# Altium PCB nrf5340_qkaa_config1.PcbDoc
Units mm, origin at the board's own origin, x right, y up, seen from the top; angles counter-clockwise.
Board outline 17 x 15 mm, 4 copper layers (Top Layer, Mid Layer 1, Mid Layer 2, Bottom Layer), stack 1.583 mm thick; 29 components, 70 nets, 204 pads, 111 vias.
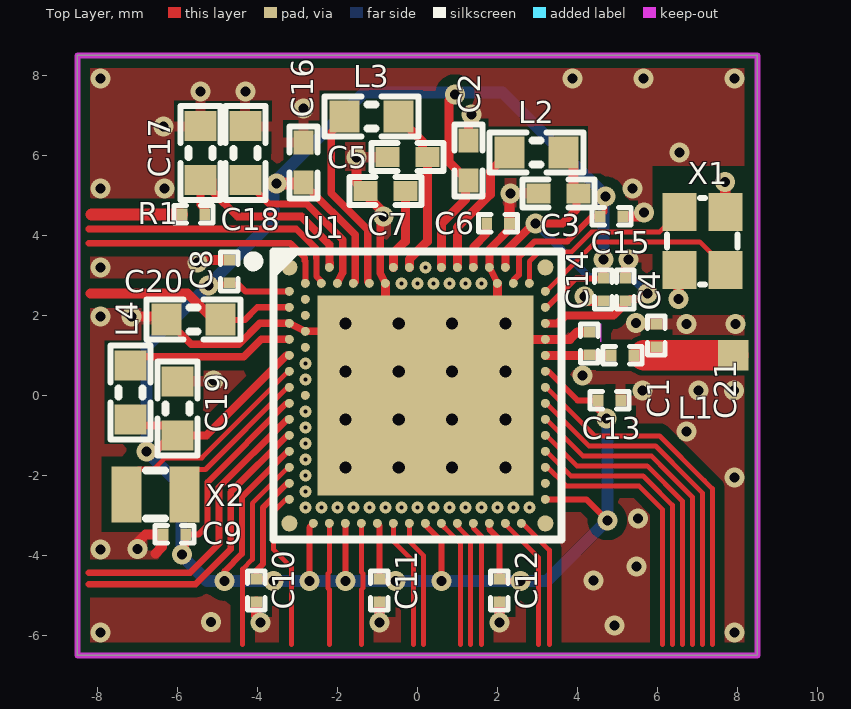
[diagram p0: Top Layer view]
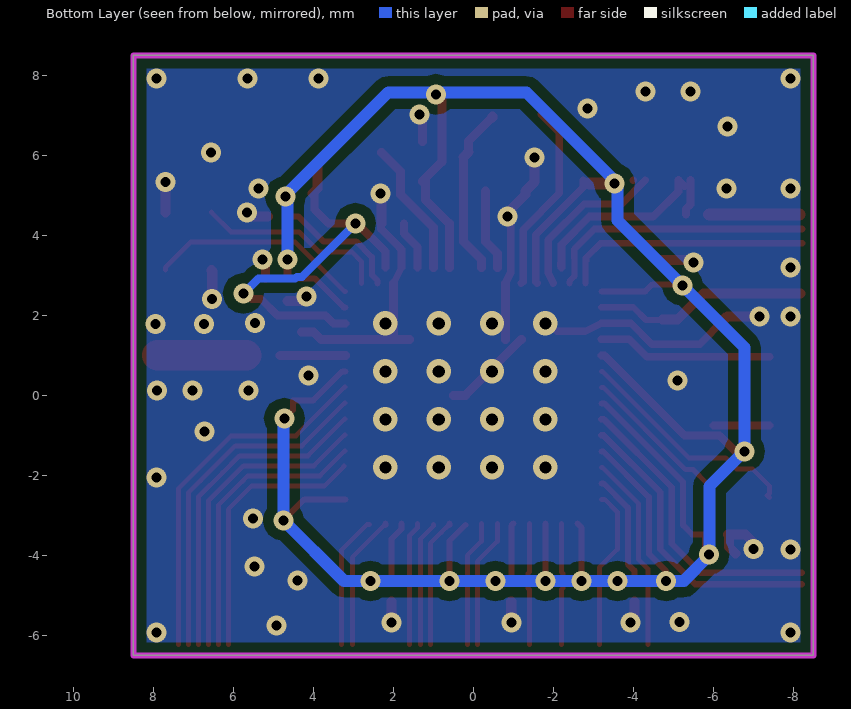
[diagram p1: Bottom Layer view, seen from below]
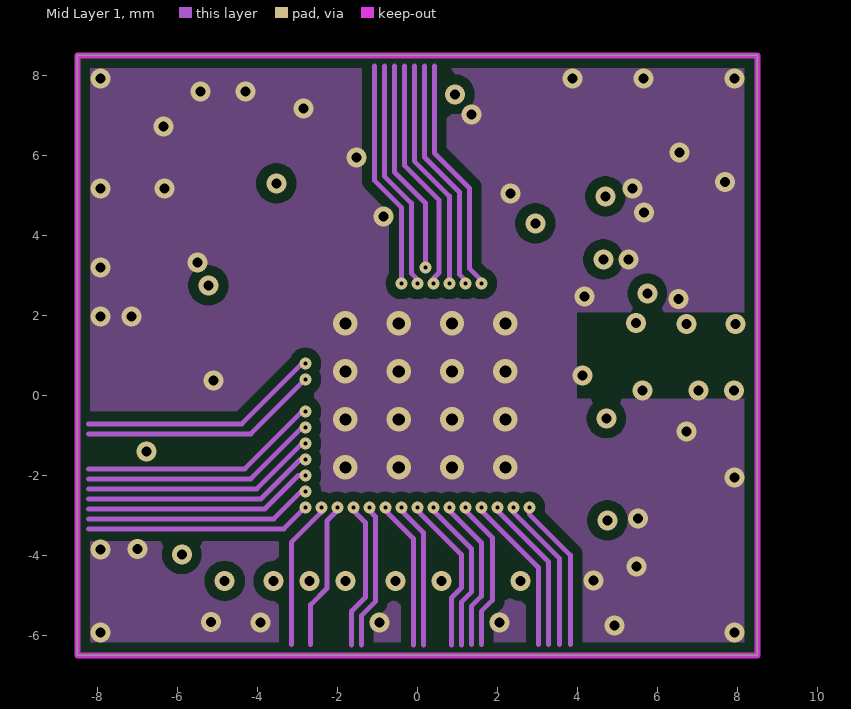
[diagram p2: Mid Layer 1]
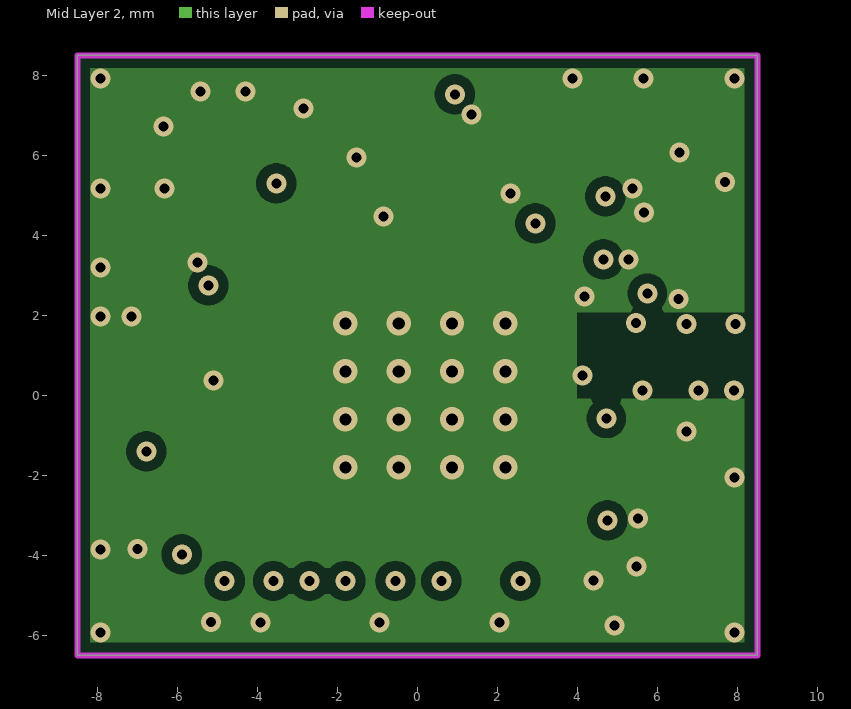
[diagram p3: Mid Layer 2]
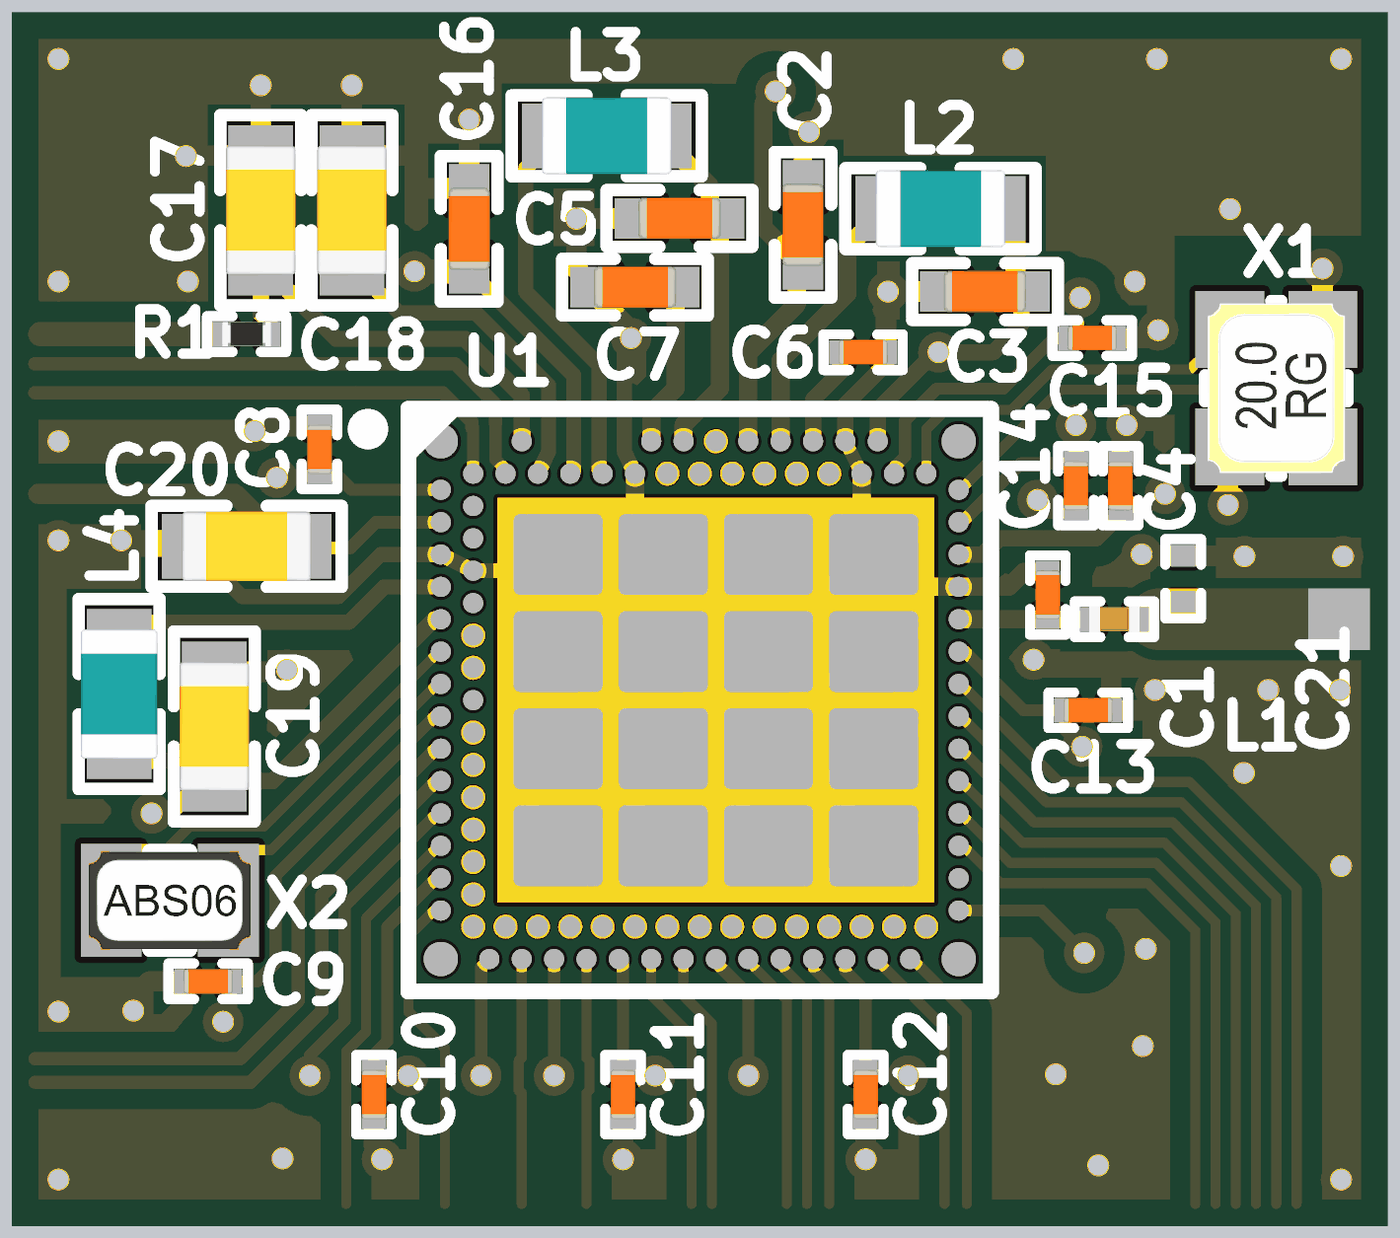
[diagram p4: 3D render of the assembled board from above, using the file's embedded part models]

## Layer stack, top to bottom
Top Solder: solder mask 0.0102, Solder Resist, Dk 3.5
Top Layer: signal copper 0.0356
Dielectric1: core 0.07, FR-4, Dk 4.8
Mid Layer 1: signal copper 0.036
Dielectric 3: prepreg 1.3, Dk 4.2
Mid Layer 2: signal copper 0.036
Dielectric 2: core 0.07, Dk 4.2
Bottom Layer: signal copper 0.0356
Bottom Solder: solder mask 0.0102, Solder Resist, Dk 3.5

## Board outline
-8.5,-6.5 8.5,-6.5 8.5,8.5 -8.5,8.5

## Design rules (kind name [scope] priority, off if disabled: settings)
Clearance Clearance_microvia [AsMM(ViaDiameter) = 0.3 vs AsMM(ViaDiameter) = 0.3] p1: gap=0.1 ignorepadtopadclearanceinfootprint=FALSE
Clearance Polygon_ANT [(InNamedPolygon('Top_Layer-GND')) or  (InNamedPolygon('Mid_Layer_1-GND')) or (InNamedPolygon('Mid_Layer_2-GND')) or (InNamedPolygon('Bottom_Layer-GND')) vs InNet('RF')] p2: gap=0.127 ignorepadtopadclearanceinfootprint=FALSE except(0: Arc-Hole Track-Hole SMDPad-Hole THPad-Hole Via-Hole Fill-Hole Poly-Hole Region-Hole Text-Hole)
Clearance Polygon [(InNamedPolygon('Top_Layer-GND')) or  (InNamedPolygon('Mid_Layer_1-GND')) or (InNamedPolygon('Mid_Layer_2-GND')) or (InNamedPolygon('Bottom_Layer-GND'))] p3: gap=0.25 ignorepadtopadclearanceinfootprint=FALSE
Clearance Clearance_Top [OnTopLayer] p4: gap=0.125 ignorepadtopadclearanceinfootprint=FALSE
Clearance [All] p5: gap=0.125 ignorepadtopadclearanceinfootprint=FALSE
ComponentClearance [All] p1 off: gap=0.254 collisioncheckmode=3 verticalgap=0.254 showdistances=FALSE
DiffPairsRouting [All] p1: maxlimit=0.193 minlimit=0.193 mostfreqgap=0.193 toplayer_minwidth=0.125 toplayer_maxwidth=0.381 toplayer_prefwidth=0.165 midlayer1_minwidth=0.125 midlayer1_maxwidth=0.381 midlayer1_prefwidth=0.165 midlayer2_minwidth=0.125 midlayer2_maxwidth=0.381 midlayer2_prefwidth=0.165 bottomlayer_minwidth=0.125 bottomlayer_maxwidth=0.381 bottomlayer_prefwidth=0.165 maxuncoupledlength=12.7
FabricationTestPointUsage TestPointUsage [All] p1: valid=0 allowmultiple=FALSE
FabricationTestpoint Testpoint [All] p1: side=3 testpointundercomponent=TRUE minsize=1.016 maxsize=2.54 preferedsize=1.524 minholesize=0 maxholesize=1.016 preferedholesize=0.813 testpointgrid=0.025 allowsidetop=TRUE allowsidebottom=TRUE usegrid=TRUE gridtolerance=0
Height [All] p1 off: minheight=0 maxheight=25.4 prefheight=12.7
HoleSize [All] p1: absolutevalues=TRUE maxlimit=4.064 minlimit=0.1 maxpercent=80.000 minpercent=20.000
MinimumAnnularRing [All] p1 off: minimumring=0.152
PolygonConnect PolygonConnect_1 [isVia and innet(gnd)] p1: connectstyle=Direct reliefconductorwidth=0.254 reliefentries=4 polygonreliefangle="90 Angle" airgapwidth=0.254
PolygonConnect [All] p2: connectstyle=Relief reliefconductorwidth=0.254 reliefentries=4 polygonreliefangle="90 Angle" airgapwidth=0.254
RoutingVias [All] p1: holewidth=0.305 width=0.61 viastyle="Through Hole" minholewidth=0.1 minwidth=0.3 maxholewidth=0.305 maxwidth=0.61
SilkToSolderMaskClearance SilkscreenOverComponentPads [IsPad] p1: minsilkscreentomaskgap=0.254 clearancetoexposedcopper=TRUE
SolderMaskExpansion [All] p1: expansion=0.076 istentingtop=FALSE
Width [All] p1: maxlimit=2 minlimit=0.125 preferedwidth=0.125 minimp=50.000000 maximp=50.000000 favimp=50.000000
23 further rules are at their usual default settings.

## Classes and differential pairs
differential pair D: +D_P -D_N

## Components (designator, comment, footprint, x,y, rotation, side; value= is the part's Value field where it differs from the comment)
C1 "0.7pF" CAPC0603X03L_C 4.3,1.3 r270 top
C2 "1.0µF" CAPC1005X04L 1.275,5.875 r90 top
C3 "1.0µF" CAPC1005X04L 3.525,5.05 r0 top
C4 "2.2nF" CAPC0603X03L_C 5.2,2.65 r90 top
C5 "1.0µF" CAPC1005X04L -0.25,5.955 r0 top
C6 "100nF" CAPC0603X03L_C 2.019,4.3 r0 top
C7 "1.0µF" CAPC1005X04L -0.8,5.105 r0 top
C8 "100nF" CAPC0603X03L_C -4.7,3.1 r90 top
C9 "100nF" CAPC0603X03L_C -6.075,-3.475 r180 top
C10 "100nF" CAPC0603X03L_C -4.026,-4.875 r270 top
C11 "100nF" CAPC0603X03L_C -0.948,-4.875 r270 top
C12 "100nF" CAPC0603X03L_C 2.05,-4.875 r270 top
C13 "100nF" CAPC0603X03L_C 4.8,-0.125 r0 top
C14 "100nF" CAPC0603X03L_C 4.65,2.65 r270 top
C15 "100nF" CAPC0603X03L_C 4.85,4.475 r0 top
C16 "1.0µF" CAPC1005X04L -2.85,5.825 r270 top
C17 "4.7µF" CAPC1608X06L -5.425,6.055 r90 top
C18 "4.7µF" CAPC1608X06L -4.3,6.055 r90 top
C19 "2.2µF" CAPC1608X06L -6,-0.325 r90 top
C20 "4.7µF" CAPC1608X06L -5.6,1.9 r180 top
C21 "N.C." CAPC0603X03L_C_NC 5.975,1.5 r270 top
L1 "2.2nH" INDC0603X03L_C 5.125,1 r180 top
L2 "10µH" INDC1608X06L 2.975,6.075 r180 top
L3 "10µH" INDC1608X06L -1.15,6.975 r180 top
L4 "10µH" INDC1608X06L -7.175,0.075 r270 top
R1 "2R2" RESC0603X03L_C -5.6,4.525 r0 top
U1 "nRF5340-QKAA" AQFN40P700X700X85_HS-99N 0,0 r0 top locked
X1 "32MHz" BT-XTAL_2016 7.125,3.854 r90 top
X2 "32.768kHz" XTAL_2012 -6.55,-2.475 r0 top

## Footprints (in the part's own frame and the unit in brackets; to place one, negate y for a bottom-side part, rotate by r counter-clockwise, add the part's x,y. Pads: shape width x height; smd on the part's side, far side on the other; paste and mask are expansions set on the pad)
AQFN40P700X700X85_HS-99N [mm] "AQFN, 98-Leads, Body 7.00x7.00mm, Pitch 0.40mm, Thermal Pad 5.4x5.0mm, IPC Medium Density"
  rect 5.4x5 smd paste-5 mask+0.05: 104(0.2,0)
  round 0.4 smd paste+0.012 mask+0.05: A1(-3.2,3.2) A31(3.2,3.2) AL1(-3.2,-3.2) AL31(3.2,-3.2)
  round 0.225 smd paste+0.012 mask+0.05: A5(-2.2,3.2) A13(-0.6,3.2) A15(-0.2,3.2) A17(0.2,3.2) A19(0.6,3.2) A21(1,3.2) A23(1.4,3.2) A25(1.8,3.2) A27(2.2,3.2) AA1(-3.2,-1) AA31(3.2,-1) AB2(-2.8,-1.2) AC1(-3.2,-1.4) AC31(3.2,-1.4) AD2(-2.8,-1.6) AE1(-3.2,-1.8) AE31(3.2,-1.8) AF2(-2.8,-2) AG1(-3.2,-2.2) AG31(3.2,-2.2) AH2(-2.8,-2.4) AJ1(-3.2,-2.6) AJ31(3.2,-2.6) AK2(-2.8,-2.8) AK4(-2.4,-2.8) AK6(-2,-2.8) AK8(-1.6,-2.8) AK10(-1.2,-2.8) AK12(-0.8,-2.8) AK14(-0.4,-2.8) AK16(0,-2.8) AK18(0.4,-2.8) AK20(0.8,-2.8) AK22(1.2,-2.8) AK24(1.6,-2.8) AK26(2,-2.8) AK28(2.4,-2.8) AK30(2.8,-2.8) AL3(-2.6,-3.2) AL5(-2.2,-3.2) AL7(-1.8,-3.2) AL9(-1.4,-3.2) AL11(-1,-3.2) AL13(-0.6,-3.2) AL15(-0.2,-3.2) AL17(0.2,-3.2) AL19(0.6,-3.2) AL21(1,-3.2) AL23(1.4,-3.2) AL25(1.8,-3.2) AL27(2.2,-3.2) AL29(2.6,-3.2) B2(-2.8,2.8) B4(-2.4,2.8) B6(-2,2.8) B8(-1.6,2.8) B10(-1.2,2.8) B12(-0.8,2.8) B14(-0.4,2.8) B16(0,2.8) B18(0.4,2.8) B20(0.8,2.8) B22(1.2,2.8) B24(1.6,2.8) B26(2,2.8) B28(2.4,2.8) B30(2.8,2.8) C1(-3.2,2.6) C31(3.2,2.6) D2(-2.8,2.4) E1(-3.2,2.2) E31(3.2,2.2) F2(-2.8,2) G1(-3.2,1.8) G31(3.2,1.8) H2(-2.8,1.6) J1(-3.2,1.4) J31(3.2,1.4) K2(-2.8,1.2) L1(-3.2,1) L31(3.2,1) M2(-2.8,0.8) N1(-3.2,0.6) N31(3.2,0.6) P2(-2.8,0.4) R1(-3.2,0.2) R31(3.2,0.2) T2(-2.8,0) U1(-3.2,-0.2) U31(3.2,-0.2) V2(-2.8,-0.4) W1(-3.2,-0.6) W31(3.2,-0.6) Y2(-2.8,-0.8)
  rrect15% 1.1x1 on Top Paste: ""(-1.75,-1.8) ""(-1.75,-0.6) ""(-1.75,0.6) ""(-1.75,1.8) ""(-0.45,-1.8) ""(-0.45,-0.6) ""(-0.45,0.6) ""(-0.45,1.8) ""(0.85,-1.8) ""(0.85,-0.6) ""(0.85,0.6) ""(0.85,1.8) ""(2.15,-1.8) ""(2.15,-0.6) ""(2.15,0.6) ""(2.15,1.8)
  silkscreen extent -4.22,-3.6 3.6,3.6, body extent -3.5,-3.5 3.5,3.5, height 0.85
BT-XTAL_2016 [mm] "Crystal 2.0 x 1.6 mm"
  rect 0.95x0.85 smd: 1(-0.725,-0.575) 2(0.725,-0.575) 3(0.725,0.575) 4(-0.725,0.575)
  silkscreen extent -1.08,-0.88 1.08,0.88, body extent -1.05,-0.85 1.05,0.85, height 0.56
CAPC0603X03L_C [mm] "Chip Capacitor, 2-Leads, Body 0.6x0.3mm, IPC High Density"
  rect 0.27x0.3 smd: 1(-0.285,0) 2(0.285,0)
  silkscreen extent -0.49,-0.22 0.49,0.22, body extent -0.3,-0.15 0.31,0.15, height 0.3
CAPC0603X03L_C_NC [mm] "Chip Capacitor, 2-Leads, Body 0.6x0.3mm, IPC High Density"
  rect 0.27x0.3 smd mask+0.05: 1(-0.285,0) 2(0.285,0)
  silkscreen extent -0.49,-0.22 0.49,0.22
CAPC1005X04L [mm] "Chip Capacitor, 2-Leads, Body 1.0x0.5mm, IPC High Density"
  rect 0.6x0.5 smd: 1(-0.5,0) 2(0.5,0)
  silkscreen extent -0.9,-0.35 0.9,0.35, body extent -0.51,-0.25 0.51,0.25, height 0.5
CAPC1608X06L [mm] "Chip Capacitor, 2-Leads, Body 1.6x0.8mm, IPC High Density"
  rect 0.75x0.8 smd: 1(-0.675,0) 2(0.675,0)
  silkscreen extent -1.17,-0.5 1.17,0.5, body extent -0.8,-0.43 0.8,0.43, height 0.8
INDC0603X03L_C [mm] "Chip Inductor, 2-Leads, Body 0.6x0.3mm, IPC High Density"
  rect 0.27x0.3 smd: 1(-0.285,0) 2(0.285,0)
  silkscreen extent -0.49,-0.22 0.49,0.22, body extent -0.31,-0.16 0.31,0.16, height 0.26
INDC1608X06L [mm] "Chip Inductor, 2-Leads, Body 1.6x0.8mm, IPC High Density"
  rect 0.75x0.8 smd: 1(-0.675,0) 2(0.675,0)
  silkscreen extent -1.17,-0.5 1.17,0.5, body extent -0.8,-0.48 0.8,0.48, height 0.8
RESC0603X03L_C [mm] "Chip Resistor, 2-Leads, Body 0.6x0.3mm, IPC High Density"
  rect 0.27x0.3 smd: 1(-0.285,0) 2(0.285,0)
  silkscreen extent -0.49,-0.22 0.49,0.22, body extent -0.3,-0.15 0.3,0.15, height 0.23
XTAL_2012 [mm] "XTAL SMD 2.0 x 1.2 mm"
  rect 0.75x1.4 smd: 1(-0.725,0) 2(0.725,0)
  silkscreen extent -0.24,-0.6 0.24,0.6, body extent -1,-0.61 1,0.61, height 0.6

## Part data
C1: library part C0201-0.7p, "Capacitor, NP0, ±0.05pF"
C2 C3 C5 C7 C16: library part C0402-1µ0-10V-X7S-GRM155C71A105KE11, "Capacitor, X7S, ±10%"
C4: library part C0201-2n2, "Capacitor, X7R, ±10%"
C6 C8 C9 C10 C11 C12 C13 C14 C15: library part C0201-100n-16V-X7S, "Capacitor, X7S, ±10%"
C17 C20: library part C0603-4µ7-10V-X7S, "Capacitor, X7S, ±10%"
C18: library part C0603-4µ7-6.3V-X7R, "Capacitor, X7R, ±10%"
C19: library part C0603-2µ2-6.3V-X7R, "Capacitor, X7R, ±10%"
C21: library part C0201-N.C., "Not mounted"
L1: library part L0201-2n2, "High frequency chip inductor, ±5%"
L2 L3: library part L0603-10µ, "Chip Inductor, IDC,min = 50 mA, ±20%"
L4: library part L0603-10µ, "Chip Inductor, IDC,min = 80 mA, ±20%"
R1: library part R0201-2R2, "Resistor, ±1%, 0.05W"
U1: "Multi-protocol Bluetooth Low Energy, IEEE 802.15.4, ANT and 2.4GHz proprietary system-on-chip"
X1: library part XTAL_SMD2016_32MHz_8pF_General, "XTAL SMD 2016, 32MHz, Cl=8pF, Total Tol: ±30ppm"
X2: library part XTAL_SMD2012_32.768kHz_9pF_General, "XTAL SMD 2012, 32.768kHz, Cl=9pF, Total Tol: ±50ppm"

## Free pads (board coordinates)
  rect 0.762x0.762 smd mask+0.076: 0(7.9,1)
  round 0.3 on Mech16: 1(-2.8,-0.8) 1(-2.8,-2.8) 1(-2.8,-2.4) 1(-2.8,-2) 1(-2.8,-1.6) 1(-2.8,-1.2) 1(-2.8,-0.4) 1(-2.8,0.4) 1(-2.8,0.8) 1(-2.4,-2.8) 1(-2,-2.8) 1(-1.6,-2.8) 1(-1.2,-2.8) 1(-0.8,-2.8) 1(-0.4,-2.8) 1(-0.4,2.8) 1(0,-2.8) 1(0,2.8) 1(0.2,3.2) 1(0.4,2.8) 1(0.4,-2.8) 1(0.8,-2.8) 1(0.8,2.8) 1(1.2,-2.8) 1(1.2,2.8) 1(1.6,-2.8) 1(1.6,2.8) 1(2,-2.8) 1(2.4,-2.8) 1(2.8,-2.8)

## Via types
v1: diameter 0.5, hole 0.25, Top Layer to Bottom Layer, tented both sides, 65 vias
v2: diameter 0.3, hole 0.1, Top Layer to Mid Layer 1, tented top, 30 vias
v3: diameter 0.61, hole 0.305, Top Layer to Bottom Layer, tented both sides, 16 vias

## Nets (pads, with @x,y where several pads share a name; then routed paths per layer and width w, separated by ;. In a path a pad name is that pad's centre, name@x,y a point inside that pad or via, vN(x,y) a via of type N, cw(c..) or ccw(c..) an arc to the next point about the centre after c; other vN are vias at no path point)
ANT: C1.2 L1.2 U1.L31 | length 1.6
  Top Layer w0.225: U1.L31 L1.2
D_N: U1.B4 | length 6.8
  Top Layer w0.15: -2.525,3.425 -2.525,2.975 -2.4,2.85 U1.B4
  Top Layer w0.165: -8.216,4.158 -3.027,4.158 -2.525,3.656 -2.525,3.425
D_P: U1.B2 | length 6.2
  Top Layer w0.15: U1.B2 -2.8,3.36
  Top Layer w0.165: -8.216,3.8 -3.175,3.8 -2.815,3.44 -2.815,3.365
GND: C1.1 C2.2 C3.1 C4.2 C5.1 C6.2 C7.1 C8.2 C9.2 C10.2 C11.2 C12.2 C13.2 C14.2 C15.2 C16.1 C17.2 C18.2 C19.2 C20.2 C21.1 U1.104 U1.A25 U1.B12 U1.B26 U1.G1 U1.H2 U1.J31 X1.2 X1.4 | length 27.1
  Top Layer w0.165: U1.A25 U1.B26
  Top Layer w0.187: C20.2 -5.657,1.281 -4.46,1.281 -3.941,1.8 U1.G1 U1.H2 U1.104@-2.1,1.6 ; -0.931,3.07 U1.B12 ; -0.931,3.074 v1@-0.931,4.4
  Top Layer w0.2: U1.A25 1.8,3.65 1.875,3.725 1.875,3.727 2.304,4.156 C6.2
  Top Layer w0.225: U1.104@-1.2,1.4 U1.104 U1.104@0.495,0 ; U1.104@-0.8,1.4 U1.B12 ; C2.2@1.275,6.35 1.275,6.925 v1@1.35,7 ; U1.104@1.6,1.4 3.815,1.4 4,1.585 C1.1 ; U1.104@2,1.4 U1.B26 ; v1(4.175,2.475) v1@4.285,2.365 ; C4.2 5.2,3.325 v1(5.275,3.4) ; v1@5.65,4.475 5.664,4.489 v1(5.664,4.572)
  Top Layer w0.25: v1@-7.1,-3.888 -7.1,-3.775 -6.8,-3.475 C9.2 -6.39,-3.505 -6.39,-3.79 -6.55,-3.95 ; v1(-5.5,3.325) -5.44,3.385 C8.2 ; C7.1@-1.3,5.025 -0.875,4.6 v1@-0.875,4.45 ; C6.2@2.3,4.3 v1@2.3,5.05 ; v1@4.285,2.365 C14.2 ; C15.2 v1@5.65,4.475
  Top Layer w0.254: v1(-7.15,1.975) -6.35,1.975 C20.2 ; C10.2 -4.026,-5.499 v1@-3.85,-5.675 ; v1(-1.525,5.95) -1.525,5.33 C7.1 ; v1(-0.948,-5.675) C11.2 ; v1(2.05,-5.675) C12.2 ; v1@6.528,2.388 6.528,3.107 X1.4 ; v1(7.696,5.334) 7.696,4.583 X1.2
  other v1: -7.925,-5.925 7.925,-5.925 4.925,-5.75 -3.926,-5.675 -5.156,-5.664 4.4,-4.625 5.475,-4.275 -7.925,-3.85 -7,-3.837 5.512,-3.073 7.925,-2.05 6.725,-0.9 5.625,0.126 7.025,0.126 7.911,0.126 -5.1,0.375 4.125,0.5 6.731,1.778 7.95,1.778 5.461,1.803 -7.925,1.975 6.528,2.413 -7.925,3.2 -0.85,4.475 2.325,5.05 -7.925,5.175 -6.325,5.175 5.375,5.175 6.553,6.071 -6.35,6.725 1.35,7.025 -2.85,7.175 -5.425,7.6 -4.3,7.6 -7.925,7.925 3.875,7.925 5.65,7.925 7.925,7.925
  other v3: -1.8,-1.8 -0.467,-1.8 0.867,-1.8 2.2,-1.8 -1.8,-0.6 -0.467,-0.6 0.867,-0.6 2.2,-0.6 -1.8,0.6 -0.467,0.6 0.867,0.6 2.2,0.6 -1.8,1.8 -0.467,1.8 0.867,1.8 2.2,1.8
NetC3_2: C3.2 C4.1 L2.1 U1.A27 U1.G31 | length 10.3
  Top Layer w0.2: U1.A27 2.2,3.593 2.907,4.3 3.625,4.3 3.975,4.65 C3.2@3.975,5.05 ; U1.G31 3.5,1.8 3.7,2 4.875,2 ; C3.2@4,5.05 C3.2@4.013,5.062 ; 4.9,2 5.315,2.415 5.54,2.415
  Top Layer w0.25: L2.1 3.65,6.05 3.9,5.8 3.9,5.175 4.013,5.062 C3.2
  Bottom Layer w0.2: v1(2.95,4.3) 4.286,2.964 4.414,2.964 4.453,2.925 5.375,2.925 v1(5.75,2.55)
NetC5_2: C5.2 L3.1 U1.A15 | length 4.3
  Top Layer w0.225: L3.1@-0.475,6.95 0.127,6.348 C5.2@0.127,6.078 ; U1.A15 -0.2,3.4 0.25,3.85 C5.2 C5.2@0.25,5.975
  Top Layer w0.25: L3.1@-0.475,6.95 L3.1 ; C5.2@0.127,6.078 C5.2
NetC6_1: C6.1 U1.A23 | length 1.2
  Top Layer w0.2: U1.A23 1.4,3.712 1.734,4.046 C6.1
NetC7_2: C7.2 U1.A13 | length 2
  Top Layer w0.225: U1.A13 -0.6,3.55 -0.3,3.85 C7.2
NetC17_1: C17.1 R1.2 U1.A5 | length 5.6
  Top Layer w0.15: U1.A5 U1.A5@-2.175,3.225
  Top Layer w0.18: U1.A5@-2.18,3.225 -2.18,3.315
  Top Layer w0.2: C17.1 -5.425,4.775 -5.315,4.665 R1.2 ; C17.1@-5.275,5.23 -5.125,5.38 -5.125,5.1 -4.491,4.466 -2.899,4.466 -2.2,3.766 U1.A5
NetC18_1: C18.1 U1.B6 | length 4.2
  Top Layer w0.187: C18.1@-4.3,5.375 -3.709,4.784 -2.767,4.784 -1.869,3.886 -1.869,3.074 ; C18.1@-4,5.375 C18.1@-4,5.38 ; U1.B6 -1.869,3.07
NetL2_2: L2.2 U1.A21 | length 3.4
  Top Layer w0.225: U1.A21 1,4.2 1.825,5.025 1.825,5.6 L2.2
NetL3_2: L3.2 U1.B10 | length 4.8
  Top Layer w0.187: L3.2@-1.7,7.025 -2.15,6.575 -2.15,5.049 -1.243,4.142 -1.243,2.843 U1.B10
NetL4_1: L4.1 U1.J1 | length 4.4
  Top Layer w0.187: L4.1@-7.412,0.962 -4.337,0.962 -3.9,1.4 U1.J1
P0.00/XL1: U1.N1 X2.1 | length 5.6
  Top Layer w0.125: X2.1@-7.4,-2.556 X2.1@-7.347,-2.503 ; X2.1@-7.4,-2.45 -7.4,-2.262 -6.975,-1.837 -6.581,-1.837 -6.306,-1.562 -5.387,-1.562 -3.224,0.6 U1.N1
P0.01/XL2: U1.R1 X2.2 | length 3.9
  Top Layer w0.125: X2.2 -5.825,-2.187 -5.489,-1.852 -5.298,-1.852 -3.246,0.2 U1.R1
P0.02/NFC1: U1.W1 | length 7.4
  Top Layer w0.165: -8.212,-4.432 -5.682,-4.432 -4.96,-3.71 -4.96,-2.297 -3.263,-0.6 U1.W1
P0.03/NFC2: U1.AA1 | length 7.4
  Top Layer w0.165: -8.212,-4.722 -5.547,-4.722 -4.67,-3.845 -4.67,-2.417 -3.253,-1 U1.AA1
P0.04/AIN0: U1.V2 | length 6
  Mid Layer 1 w0.125: -8.225,-1.837 -4.315,-1.837 -2.877,-0.4 v2(-2.8,-0.4)
P0.05/AIN1: U1.Y2 | length 6
  Mid Layer 1 w0.125: -8.225,-2.088 -4.165,-2.088 -2.877,-0.8 v2(-2.8,-0.8)
P0.06/AIN2: U1.AB2 | length 5.9
  Mid Layer 1 w0.125: -8.225,-2.338 -4.015,-2.338 -2.877,-1.2 v2(-2.8,-1.2)
P0.07/AIN3: U1.AD2 | length 5.8
  Mid Layer 1 w0.125: -8.225,-2.588 -3.911,-2.588 -2.924,-1.6 v2(-2.8,-1.6)
P0.08/TRACEDATA3: U1.AH2 | length 5.7
  Mid Layer 1 w0.125: -8.225,-3.088 -3.588,-3.088 -2.9,-2.4 v2(-2.8,-2.4)
P0.09/TRACEDATA2: U1.AJ1 | length 4
  Top Layer w0.125: U1.AJ1 -3.282,-2.6 -3.6,-2.918 -3.6,-3.85 -3.15,-4.3 -3.15,-6.225
P0.10/TRACEDATA1: U1.AK2 | length 5.6
  Mid Layer 1 w0.125: -8.225,-3.338 -3.338,-3.338 v2(-2.8,-2.8)
P0.11/TRACEDATA0: U1.AK4 | length 3.7
  Mid Layer 1 w0.125: -3.15,-6.225 -3.15,-3.673 -2.4,-2.924 v2(-2.4,-2.8)
P0.12/TRACECLK: U1.AK6 | length 3.7
  Mid Layer 1 w0.125: -2.667,-6.225 -2.667,-5.232 -2.261,-4.826 -2.261,-3.138 -2,-2.877 v2(-2,-2.8)
P0.13/QSPI0: U1.AL5 | length 3.1
  Top Layer w0.125: -2.2,-6.225 -2.2,-4.859 -2.238,-4.821 -2.238,-4.459 -2.2,-4.421 U1.AL5
P0.14/QSPI1: U1.AK8 | length 3.7
  Mid Layer 1 w0.125: -1.65,-6.237 -1.65,-5.404 -1.3,-5.054 -1.3,-3.177 -1.538,-2.94 -1.538,-2.862 v2(-1.6,-2.8)
P0.15/QSPI2: U1.AK10 | length 3.6
  Mid Layer 1 w0.125: -1.4,-6.237 -1.4,-5.508 -1.05,-5.158 -1.05,-3.027 -1.138,-2.94 -1.138,-2.862 v2(-1.2,-2.8)
P0.16/QSPI3: U1.AL9 | length 3.1
  Top Layer w0.125: -1.4,-6.225 -1.4,-4.859 -1.362,-4.821 -1.362,-4.459 -1.4,-4.421 U1.AL9
P0.17/QSPI_CLK: U1.AK12 | length 3.7
  Mid Layer 1 w0.125: v2(-0.8,-2.8) -0.738,-2.862 -0.738,-2.94 -0.1,-3.577 -0.1,-6.237
P0.18/QSPI_CS: U1.AK14 | length 3.7
  Mid Layer 1 w0.125: v2(-0.4,-2.8) -0.338,-2.862 -0.338,-2.94 0.15,-3.427 0.15,-6.237
P0.19: U1.AL13 | length 3.2
  Top Layer w0.125: U1.AL13 -0.6,-3.65 -0.1,-4.15 -0.1,-6.225
P0.20: U1.AK16 | length 4
  Mid Layer 1 w0.125: v2(0,-2.8) 0.062,-2.862 0.062,-2.94 1.1,-3.977 1.1,-4.818 0.85,-5.068 0.85,-6.237
P0.21: U1.AL15 | length 3.2
  Top Layer w0.125: U1.AL15 -0.2,-3.65 0.15,-4 0.15,-6.225
P0.22: U1.AK18 | length 4
  Mid Layer 1 w0.125: v2@0.363,-2.837 v2(0.4,-2.8) 0.4,-2.877 1.35,-3.827 1.35,-4.921 1.1,-5.171 1.1,-6.237
P0.23: U1.AK20 | length 3.9
  Mid Layer 1 w0.125: v2(0.8,-2.8) 0.8,-2.877 1.6,-3.677 1.6,-5.025 1.35,-5.275 1.35,-6.225
P0.24: U1.AL27 | length 3.4
  Top Layer w0.125: U1.AL27@2.2,-3.224 3.025,-4.049 3.025,-6.225
  Top Layer w0.15: U1.AL27@2.2,-3.242 2.2,-3.224 U1.AL27
P0.25/AIN4: U1.AK28 | length 3.9
  Mid Layer 1 w0.125: v2(2.4,-2.8) 2.4,-2.924 3.55,-4.074 3.55,-6.234
P0.26/AIN5: U1.AL29 | length 3.3
  Top Layer w0.125: U1.AL29@2.6,-3.224 2.653,-3.224 3.3,-3.871 3.3,-6.225
P0.27/AIN6: U1.AK30 | length 3.9
  Mid Layer 1 w0.125: v2(2.8,-2.8) 2.8,-2.97 3.825,-3.995 3.825,-6.234
P0.28/AIN7: U1.AE31 | length 6.7
  Top Layer w0.125: U1.AE31@3.228,-1.772 3.719,-2.263 5.538,-2.263 6.125,-2.85 6.125,-6.225
P0.29: U1.U31 | length 8.6
  Top Layer w0.125: U1.U31@3.212,-0.188 4.287,-1.263 5.952,-1.263 6.825,-2.136 7.125,-2.436 7.125,-6.225
P0.30: U1.B24 | length 5.9
  Mid Layer 1 w0.125: 0.425,8.234 0.425,6.061 1.3,5.186 1.3,3.177 1.6,2.877 v2(1.6,2.8)
P0.31: U1.B22 | length 5.9
  Mid Layer 1 w0.125: 0.175,8.234 0.175,5.957 1.05,5.082 1.05,3.027 1.2,2.877 v2(1.2,2.8)
P1.00: U1.M2 | length 6.1
  Mid Layer 1 w0.125: -8.225,-0.712 -4.39,-0.712 -2.877,0.8 v2(-2.8,0.8)
P1.01: U1.P2 | length 6
  Mid Layer 1 w0.125: -8.225,-0.962 -4.162,-0.962 v2(-2.8,0.4)
P1.02/TWI: U1.AE1 | length 4.9
  Top Layer w0.125: -4.369,-6.225 -4.369,-4.344 -4.125,-4.1 -4.125,-2.701 -3.224,-1.8 U1.AE1
P1.03/TWI: U1.AF2 | length 5.8
  Mid Layer 1 w0.125: -8.225,-2.838 -3.808,-2.838 -2.97,-2 v2(-2.8,-2)
P1.04: U1.AL19 | length 3.5
  Top Layer w0.125: U1.AL19@0.6,-3.242 0.617,-3.242 0.801,-3.426 ; U1.AL19@0.6,-3.224 0.801,-3.425 ; 1.075,-6.225 1.075,-3.7 0.801,-3.426
  Top Layer w0.15: U1.AL19@0.6,-3.242 U1.AL19
P1.05: U1.AK22 | length 3.8
  Mid Layer 1 w0.125: v2(1.2,-2.8) 1.2,-2.877 1.875,-3.552 1.875,-5.125 1.6,-5.4 1.6,-6.225
P1.06: U1.AL21 | length 3.1
  Top Layer w0.125: U1.AL21@1,-3.224 1,-3.271 1.051,-3.321 ; 1.051,-3.322 1.325,-3.596 1.325,-6.225
P1.07: U1.AK24 | length 4
  Mid Layer 1 w0.125: v2(1.6,-2.8) 1.6,-2.877 3.025,-4.302 3.025,-6.234
P1.08: U1.AL23 | length 3.1
  Top Layer w0.125: U1.AL23 1.4,-3.317 1.6,-3.517 1.6,-6.225
P1.09: U1.AK26 | length 4
  Mid Layer 1 w0.125: v2(2,-2.8) 2,-2.877 3.275,-4.152 3.275,-6.234
P1.10: U1.R31 | length 9.1
  Top Layer w0.125: U1.R31@3.213,0.212 4.438,-1.013 6.055,-1.013 7.175,-2.132 7.375,-2.332 7.375,-6.225
P1.11: U1.B20 | length 5.8
  Mid Layer 1 w0.125: -0.075,8.234 -0.075,5.854 0.8,4.979 v2(0.8,2.8)
P1.12: U1.B18 | length 5.8
  Mid Layer 1 w0.125: -0.325,8.234 -0.325,5.75 0.538,4.887 0.538,3.06 0.4,2.923 v2(0.4,2.8)
P1.13: U1.A17 | length 5.4
  Mid Layer 1 w0.125: -0.575,8.234 -0.575,5.582 0.2,4.807 v2(0.2,3.2)
P1.14: U1.B16 | length 5.8
  Mid Layer 1 w0.125: -0.825,8.234 -0.825,5.479 -0.15,4.804 -0.15,3.05 0,2.9 v2(0,2.8)
P1.15: U1.B14 | length 5.7
  Mid Layer 1 w0.125: -1.075,8.234 -1.075,5.375 -0.4,4.7 v2@-0.4,2.825
  other v2: -0.4,2.8
R\E\S\E\T\: U1.AC31 | length 7.2
  Top Layer w0.125: U1.AC31@3.212,-1.388 3.837,-2.013 5.641,-2.013 5.764,-2.136 6.375,-2.746 6.375,-6.225
RF: C21.2 L1.1 pad.0 | length 2.2
  Top Layer w0.762: 5.675,1 pad.0
SWDCLK: U1.W31 | length 8.2
  Top Layer w0.125: U1.W31@3.212,-0.588 4.137,-1.513 5.848,-1.513 6.268,-1.932 6.875,-2.539 6.875,-6.225
SWDIO: U1.AA31 | length 7.7
  Top Layer w0.125: U1.AA31@3.212,-0.988 3.987,-1.763 5.745,-1.763 6.625,-2.643 6.625,-6.225
VBUS: R1.1 | length 2.3
  Top Layer w0.3: -8.148,4.525 R1.1
VDD_HV: C20.1 U1.E1 | length 5.4
  Top Layer w0.158: C20.1@-4.725,1.9 -4.708,1.883 -4.317,1.883 -4,2.2 U1.E1
  Top Layer w0.25: -8.173,2.55 -5.75,2.55 -5.1,1.9 C20.1 C20.1@-4.725,1.9
VDD_NRF: C2.1 C8.1 C9.1 C10.1 C11.1 C12.1 C13.1 C14.1 C15.1 C16.2 C19.1 L4.2 U1.A19 U1.AC1 U1.AG1 U1.AJ31 U1.AL3 U1.AL7 U1.AL11 U1.AL17 U1.AL25 U1.B8 U1.B28 U1.C1 U1.E31 U1.L1 U1.N31 U1.U1 | length 84
  Top Layer w0.15: v1@-5.79,-3.975 C9.1 -5.467,-3.475 -5.243,-3.25 -5.243,-2.168 -3.275,-0.2 U1.U1 ; v1@-5.225,2.775 -4.475,2.775 -4.3,2.6 U1.C1 ; v1(-4.818,-4.64) -4.818,-4.393 -4.388,-3.963 -4.388,-2.546 -3.242,-1.4 U1.AC1 ; C10.1 -4.026,-4.382 -3.863,-4.218 -3.863,-2.809 -3.253,-2.2 U1.AG1 ; C10.1@-3.95,-4.59 -3.652,-4.59 v1(-3.602,-4.64) v1@-3.475,-4.64 ; v1(-2.702,-4.64) -2.702,-3.302 U1.AL3 ; v1(-1.8,-4.64) U1.AL7 ; U1.AL11 -0.95,-3.25 -0.95,-3.514 ; C11.1@-0.948,-4.64 v1@-0.6,-4.64 ; C11.1 -0.948,-3.776 -0.948,-3.514 ; U1.AL17@0.2,-3.242 0.6,-3.642 v1(0.6,-4.64) ; U1.AL25 1.8,-3.346 2.05,-3.596 C12.1 2.1,-4.64 v1(2.575,-4.64) ; U1.B28 2.4,2.875 2.537,3.012 2.537,3.457 2.931,3.85 3.749,3.85 4.374,4.475 C15.1 4.675,4.585 v1@4.675,4.975 ; U1.AJ31 4.225,-2.6 v1(4.75,-3.125) ; U1.N31 3.277,0.6 4.002,-0.125 C13.1 4.515,-0.365 v1(4.725,-0.575) ; U1.E31 3.242,2.2 3.967,2.925 4.64,2.925 C14.1
  Top Layer w0.187: C16.2@-2.75,5.38 -2.75,5.208 -1.557,4.015 -1.557,2.843 U1.B8
  Top Layer w0.2: L4.2@-7.4,-0.75 C19.1@-6,-0.75 ; v1(-6.775,-1.4) -6.55,-1.4 -6.15,-1 C19.1 -5.277,-1 -3.277,1 U1.L1
  Top Layer w0.203: C14.1 v1(4.65,3.4)
  Top Layer w0.225: U1.A19 0.6,4.295 1.2,4.895 C2.1@1.2,5.35 ; v1(0.938,7.525) 0.787,7.375 0.787,5.838 C2.1@1.275,5.35
  Top Layer w0.3: v1(-3.525,5.3) C16.2@-2.9,5.3
  Bottom Layer w0.3: v1(4.65,3.4) 4.65,5.05 2.125,7.575 -1.325,7.575 -3.6,5.3 -3.6,4.375 v1(-5.225,2.75) -6.775,1.2 v1(-6.775,-1.4) -5.9,-2.275 -5.9,-4 -5.26,-4.64 v1(-4.818,-4.64) v1(-3.602,-4.64) v1(-2.702,-4.64) v1(-1.8,-4.64) 3.235,-4.64 v1(4.75,-3.125) 4.75,-0.6 v1(4.725,-0.575)
  other v1: -0.55,-4.64 -5.89,-3.975 4.7,4.975
XC1: U1.C31 X1.1 | length 5.3
  Top Layer w0.125: U1.C31 3.224,2.6 4.462,3.838 7.059,3.838 7.7,3.197 X1.1
XC2: U1.B30 X1.3 | length 4.8
  Top Layer w0.125: U1.B30 2.8,3.348 3.039,3.588 3.858,3.588 4.358,4.088 6.058,4.088 X1.3
pads on no net: U1. U1.A1 U1.A31 U1.AG31 U1.AL1 U1.AL31 U1.D2 U1.F2 U1.K2 U1.T2

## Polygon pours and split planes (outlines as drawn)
GND on Top Layer "Top_Layer-GND" (solid, remove dead copper, pour order 1000): -15.274,14.151 -15.275,-15.849 12.225,-15.849 12.226,14.151
GND on Bottom Layer "Bottom_Layer-GND" (solid, remove dead copper, pour order 1001): -15,15 -15,-15 12.5,-15 12.5,15
GND on Mid Layer 2 "Mid_Layer_2-GND" (solid, remove dead copper, pour order 1002): -15,15 -15,-15 12.5,-15 12.5,15
GND on Mid Layer 1 "Mid_Layer_1-GND" (solid, remove dead copper, pour order 1004): -15,15 -15,-15 12.5,-15 12.5,15

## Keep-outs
Top Layer:
  rectangle: 4.575,1.35 4.6,1.775
Keep-Out Layer:
  the board outline again, w0.15

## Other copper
Top Layer:
  pour cut-out: 0.127,7.62 0.508,7.62 0.508,7.569 0.127,7.569
  pour cut-out: 5.867,5.74 5.867,2.007 8.179,2.007 8.179,5.74
Mid Layer 1:
  pour cut-out: 9.9,-0.083 3.982,-0.083 3.982,2.083 9.9,2.083
Mid Layer 2:
  pour cut-out: 9.9,-0.083 3.982,-0.083 3.982,2.083 9.9,2.083

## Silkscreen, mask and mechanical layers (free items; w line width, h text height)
Mechanical 1:
  the board outline again, w0.15

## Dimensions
8.5,-6.5 to -8.5,-6.5 on Mechanical 3
8.5,-6.5 to 8.5,8.5 on Mechanical 3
